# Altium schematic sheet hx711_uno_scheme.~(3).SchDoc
size A4
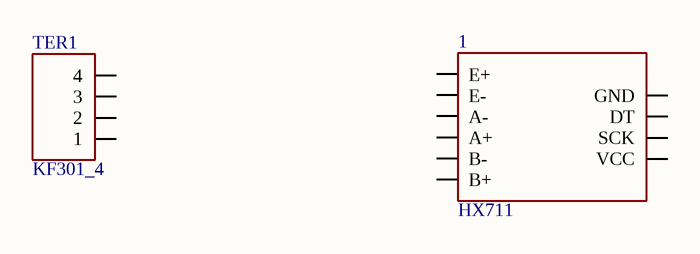
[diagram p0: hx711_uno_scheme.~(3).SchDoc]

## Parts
1  HX711  [HX711]
TER1  KF301_4  [KF304_4]

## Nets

Not connected (* = marked no-connect by the designer): 1 1(E+) 2(E-) 3(A-) 4(A+) 5(B-) 6(B+) 7(GND) 8(DT) 9(SCK) 10(VCC); TER1 1 2 3 4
